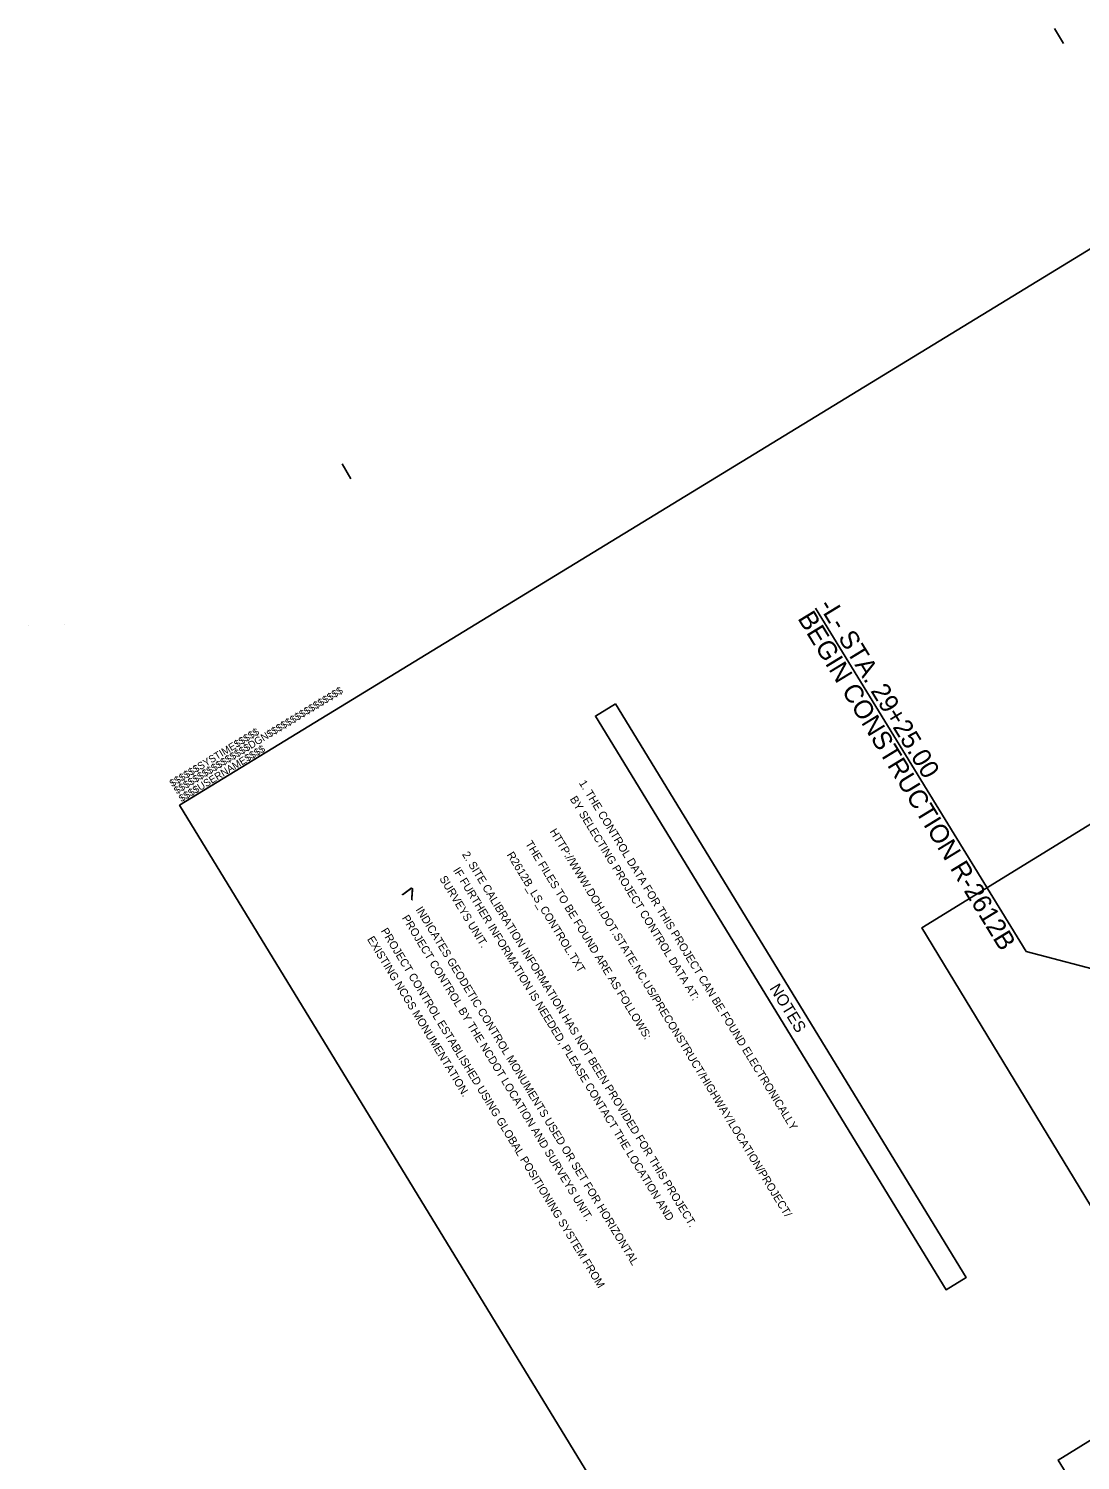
# Model space of a CAD drawing. Extents: x 1771071 to 1790027, y 804210 to 823391.
# Drawn here: x 1771071 to 1778956, y 812655 to 823391 of the extents above; entities that cross this region are included whole.
import ezdxf

# ---------------------------------------------------------------- set-up
doc = ezdxf.new("R2010")
doc.units = 0
for name, color, linetype in [('Old_Level_2', 7, 'Continuous'), ('Old_Level_57', 7, 'Continuous'), ('Prop Approach Slab', 7, 'Continuous'), ('Prop CMT Guardrail Graphics', 7, 'Continuous'), ('Prop Conc 2ft 6in Curb and Gutter', 7, 'Continuous'), ('Prop Conc Shoulder Berm Gutter', 7, 'Continuous'), ('Prop Horizontal Alignment', 7, 'Continuous'), ('Scratch_Level_7', 7, 'Continuous')]:
    doc.layers.add(name, color=color, linetype=linetype)

msp = doc.modelspace()

# ---------------------------------------------------------------- linework, layer by layer
at = {"layer": 'Prop CMT Guardrail Graphics'}
msp.add_lwpolyline([(1779934, 817129), (1779441, 817678), (1777767, 816648), (1779808, 813287), (1778788, 812657), (1781191, 808757), (1783068, 810931), (1784925, 813316), (1781884, 818311)], close=True, dxfattribs=at)
at = {"layer": 'Prop Conc 2ft 6in Curb and Gutter'}
for points in [[(1789712, 809923), (1781551, 823279), (1772202, 817567), (1780362, 804210)], [(1775471, 818328), (1778100, 814026), (1777949, 813934), (1775320, 818236)]]:
    msp.add_lwpolyline(points, close=True, dxfattribs=at)
at = {"layer": 'Prop Conc Shoulder Berm Gutter'}
for p, q in [((1778549, 816470), (1776971, 819044)), ((1779932, 816106), (1778549, 816470))]:
    msp.add_line(p, q, dxfattribs=at)
at = {"layer": 'Prop Horizontal Alignment'}
for p, q in [((1778762, 823391), (1778830, 823280)), ((1773420, 820127), (1773487, 820016)), ((1771071, 818918), (1771071, 818918)), ((1771341, 818924), (1771341, 818924))]:
    msp.add_line(p, q, dxfattribs=at)

# ---------------------------------------------------------------- texts
at = {"layer": 'Old_Level_2'}
for s, rotation, p in [('1. THE CONTROL DATA FOR THIS PROJECT CAN BE FOUND ELECTRONICALLY', 301.4249, (1775194, 817734)), ('   BY SELECTING PROJECT CONTROL DATA AT:', 301.4249, (1775091, 817671)), ('HTTP://WWW.DOH.DOT.STATE.NC.US/PRECONSTRUCT/HIGHWAY/LOCATION/PROJECT/', 301.4249, (1774974, 817370)), ('THE FILES TO BE FOUND ARE AS FOLLOWS:', 301.4249, (1774792, 817280)), ('2. SITE CALIBRATION INFORMATION HAS NOT BEEN PROVIDED FOR THIS PROJECT.', 301.4249, (1774318, 817199)), ('R2612B_LS_CONTROL.TXT', 301.4249, (1774653, 817196)), ('   IF FURTHER INFORMATION IS NEEDED, PLEASE CONTACT THE LOCATION AND', 301.4249, (1774216, 817137)), ('   SURVEYS UNIT.', 301.4249, (1774113, 817074)), ('PROJECT CONTROL BY THE NCDOT LOCATION AND SURVEYS UNIT.', 301.3197, (1773867, 816722)), ('INDICATES GEODETIC CONTROL MONUMENTS USED OR SET FOR HORIZONTAL', 301.3197, (1773970, 816785)), ('PROJECT CONTROL ESTABLISHED USING GLOBAL POSITIONING SYSTEM FROM', 301.3197, (1773709, 816625)), ('EXISTING NCGS MONUMENTATION.', 301.3197, (1773606, 816563))]:
    msp.add_text(s, height=60, rotation=rotation, dxfattribs=at).set_placement(p)
at = {"layer": 'Old_Level_57'}
msp.add_text('>', height=130, rotation=61.3341, dxfattribs=at).set_placement((1773957, 816837))
at = {"layer": 'Prop Approach Slab'}
msp.add_text('NOTES', height=87, rotation=301.4249, dxfattribs=at).set_placement((1776622, 816195))
at = {"layer": 'Prop Horizontal Alignment'}
for s, p in [('$$$$$$$$$$$$$$$$DGN$$$$$$$$$$$$$$$$', (1772181, 817648)), ('$$$$$$SYSTIME$$$$$', (1772148, 817702)), ('$$$$USERNAME$$$$', (1772217, 817589))]:
    msp.add_text(s, height=54.78, rotation=31.4249, dxfattribs=at).set_placement(p)
at = {"layer": 'Scratch_Level_7'}
for s, p in [('-L- STA. 29+25.00', (1776989, 819065)), ('BEGIN CONSTRUCTION R-2612B', (1776832, 818969))]:
    msp.add_text(s, height=140, rotation=301.4017, dxfattribs=at).set_placement(p)

doc.saveas('drawing.dxf')
